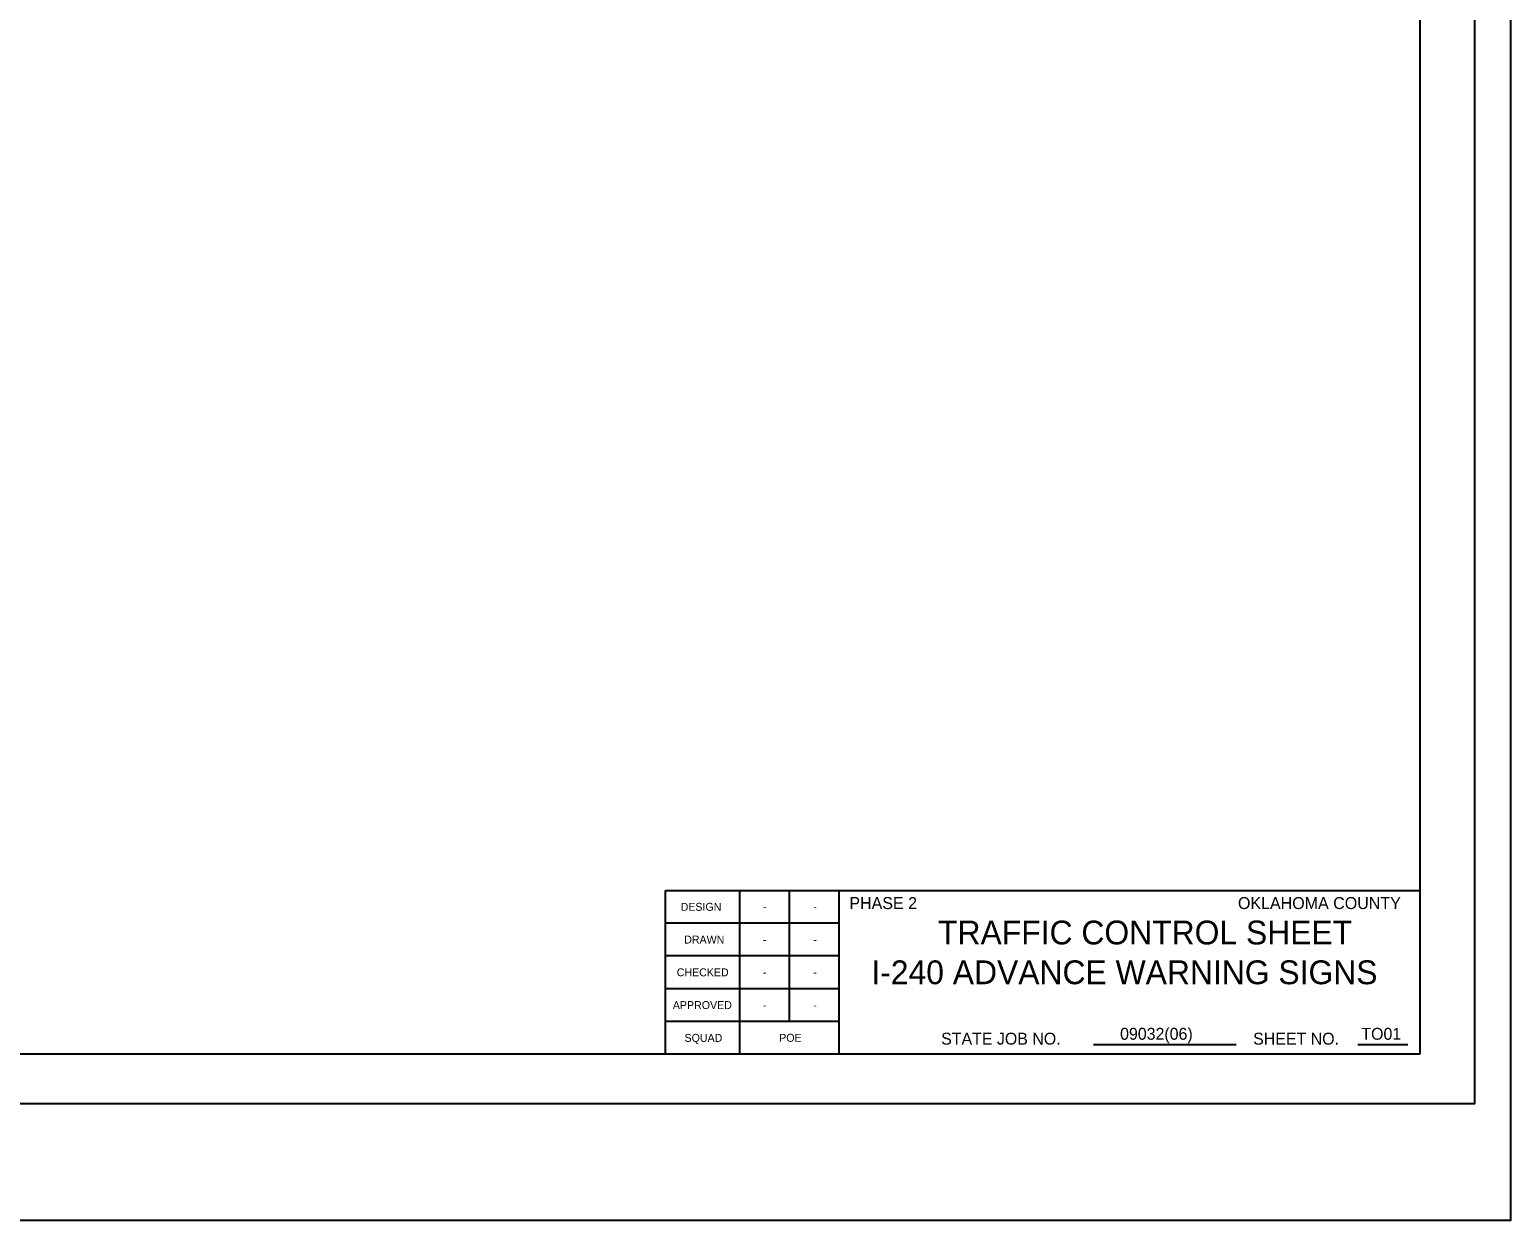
# Model space of a CAD drawing. Extents: x 2155255 to 2162649, y 140388 to 141878.
# Drawn here: x 2157209 to 2157955, y 140388 to 140988 of the extents above; entities that cross this region are included whole.
import ezdxf

# ---------------------------------------------------------------- set-up
doc = ezdxf.new("R2010")
doc.units = 0
for name, color, linetype in [('SHT_Plot_Shape_Full', 7, 'Continuous'), ('SHT_Plot_Shape_Half', 7, 'Continuous'), ('SHT_Sheet_Border', 7, 'Continuous'), ('SHT_Standard_Sheet_Lines', 7, 'Continuous'), ('SHT_Standard_Sheet_Txt', 7, 'Continuous')]:
    doc.layers.add(name, color=color, linetype=linetype)

msp = doc.modelspace()

# ---------------------------------------------------------------- linework, layer by layer
at = {"layer": 'SHT_Plot_Shape_Full'}
msp.add_lwpolyline([(2156155.34, 141588.17), (2157955.34, 141588.17), (2157955.34, 140388.17), (2156155.34, 140388.17)], close=True, dxfattribs=at)
at = {"layer": 'SHT_Plot_Shape_Half'}
msp.add_lwpolyline([(2156237.22, 141546.92), (2157937.22, 141546.92), (2157937.22, 140446.92), (2156237.22, 140446.92)], close=True, dxfattribs=at)
at = {"layer": 'SHT_Sheet_Border'}
for p, q in [((2157529.72, 140554.42), (2157909.72, 140554.43)), ((2157529.72, 140471.92), (2157529.72, 140554.42)), ((2157617.22, 140471.92), (2157617.22, 140554.46))]:
    msp.add_line(p, q, dxfattribs=at)
msp.add_lwpolyline([(2157909.72, 140471.92), (2156334.72, 140471.92), (2156334.72, 141521.92), (2157909.72, 141521.92)], close=True, dxfattribs=at)
at = {"layer": 'SHT_Standard_Sheet_Lines'}
for p, q in [((2157567.22, 140471.92), (2157567.22, 140554.46)), ((2157592.22, 140488.43), (2157592.22, 140554.46)), ((2157745.25, 140476.73), (2157817.27, 140476.73)), ((2157878.49, 140476.73), (2157903.62, 140476.73))]:
    msp.add_line(p, q, dxfattribs=at)
for points in [[(2157617.22, 140537.92), (2157529.72, 140537.92)], [(2157617.22, 140521.42), (2157529.72, 140521.42)], [(2157617.22, 140504.92), (2157529.72, 140504.92)], [(2157617.22, 140488.42), (2157529.72, 140488.42)]]:
    msp.add_lwpolyline(points, dxfattribs=at)

# ---------------------------------------------------------------- texts
at = {"layer": 'SHT_Standard_Sheet_Txt'}
for s, height, p in [('PHASE 2', 6.035, (2157622.32, 140545.04)), ('OKLAHOMA COUNTY', 6.0352, (2157818.09, 140545.04))]:
    msp.add_text(s, height=height, rotation=0, dxfattribs=at).set_placement(p)
for s, height, p in [('DESIGN', 4, (2157537.33, 140544.17)), ('-', 4, (2157578.74, 140544.19)), ('-', 4, (2157604.16, 140544.19)), ('TRAFFIC CONTROL SHEET', 12, (2157667.02, 140527.22)), ('DRAWN', 4, (2157539.12, 140527.67)), ('-', 4, (2157578.74, 140527.69)), ('-', 4, (2157604.16, 140527.69)), ('I-240 ADVANCE WARNING SIGNS', 12, (2157633.39, 140507.18)), ('CHECKED', 4, (2157535.36, 140511.16)), ('-', 4, (2157578.74, 140511.18)), ('-', 4, (2157604.16, 140511.18)), ('APPROVED', 4, (2157533.4, 140494.65)), ('-', 4, (2157578.74, 140494.67)), ('-', 4, (2157604.16, 140494.67)), ('SQUAD', 4, (2157539.29, 140478.14)), ('POE', 4, (2157586.97, 140478.17)), ('STATE JOB NO.', 6, (2157668.57, 140476.73)), ('09032(06)', 6, (2157758.72, 140479.19)), ('SHEET NO. ', 6, (2157825.75, 140476.73)), ('TO01', 6, (2157880.27, 140479.19))]:
    msp.add_text(s, height=height, dxfattribs=at).set_placement(p)

doc.saveas('drawing.dxf')
